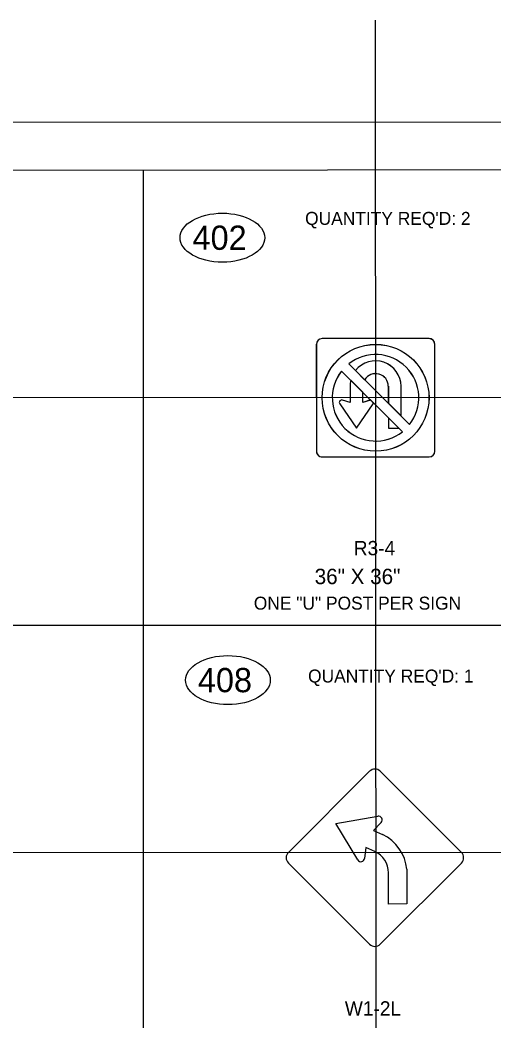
# Model space of a CAD drawing. Extents: x 1977705 to 1981198, y 827296 to 829291.
# Drawn here: x 1979660.1 to 1979879, y 828320.6 to 828783.1 of the extents above; entities that cross this region are included whole.
import ezdxf

# ---------------------------------------------------------------- set-up
doc = ezdxf.new("R2010")
doc.units = 0
for name, color, linetype in [('Level 3', 7, 'Continuous'), ('Level 34', 7, 'Continuous'), ('Level 43', 7, 'Continuous'), ('Level 45', 7, 'Continuous'), ('Level 7', 7, 'Continuous')]:
    doc.layers.add(name, color=color, linetype=linetype)

# ---------------------------------------------------------------- blocks, each defined once
blk = doc.blocks.new('Exist No U Turn')
at = {"layer": 'Level 45'}
for p, q in [((-62.7, 56.3), (-62.7, -56.6)), ((56.3, 62.3), (-56.6, 62.3)), ((62.3, -56.6), (62.3, 56.3)), ((-28.5, 35.7), (35.7, -28.5)), ((-28.5, 35.7), (-28.5, 35.7)), ((-36.1, 28.1), (28.1, -36.1)), ((-36.1, 28.1), (-36.1, 28.1)), ((-21.3, 28.5), (-11.7, 18.9)), ((-21.3, 28.5), (-11.7, 18.9)), ((-21.3, 28.5), (-11.7, 18.9)), ((-11.7, 18.9), (-11.7, 18.9)), ((-11.7, 18.9), (-11.7, 18.9)), ((-11.7, 18.9), (-11.7, 18.9)), ((-2.2, -5.7), (-5.4, -2.5)), ((-2.7, -6.7), (-2.7, -6.7)), ((-2.7, -6.7), (-2.7, -6.7)), ((-56.6, -62.7), (56.3, -62.7))]:
    blk.add_line(p, q, dxfattribs=at)
for points in [[(-27, 11.9), (-27, -5.1), (-35, -2.6)], [(-27, 11.9), (-27, -5.1), (-35, -2.6)], [(-27, 11.9), (-27, -5.1), (-35, -2.6)], [(-2.2, -5.7), (-5.4, -2.5), (-13.6, -5.1), (-13.6, 5.7), (-26.3, 18.3)], [(-5.7, -2.6), (-13.6, -5.1), (-13.6, 5.7), (-26.3, 18.3)], [(-2.2, -5.7), (-5.4, -2.5), (-13.6, -5.1), (-13.6, 5.7), (-26.3, 18.3)], [(13.3, 11.9), (13.3, -6), (26.7, -19.5), (26.7, 11.9)], [(13.3, 11.9), (13.3, -6), (26.7, -19.5), (26.7, 11.9)], [(13.3, 11.9), (13.3, -6), (26.7, -19.5), (26.7, 11.9)], [(-38, -6.7), (-20.3, -32.4), (-2.7, -6.7)], [(-38, -6.7), (-20.3, -32.4), (-2.7, -6.7)], [(-38, -6.7), (-20.3, -32.4), (-2.7, -6.7)]]:
    blk.add_lwpolyline(points, dxfattribs=at)
blk.add_lwpolyline([(13.3, -21.2), (13.3, -32.4), (24.5, -32.4)], close=True, dxfattribs=at)
blk.add_lwpolyline([(13.3, -21.2), (13.3, -32.4), (24.5, -32.4)], close=True, dxfattribs=at)
blk.add_lwpolyline([(13.3, -21.2), (13.3, -32.4), (24.5, -32.4)], close=True, dxfattribs=at)
blk.add_circle((-0.2, -0.2), 56.4, dxfattribs=at)
for centre, radius, start, end in [((-56.6, 56.3), 6.05, 90, 180), ((56.3, 56.3), 6.05, 0, 90), ((-0.2, -0.2), 45.7, 321.7553, 128.2447), ((-0.2, 11.9), 26.9, 359.9928, 141.788), ((-0.2, 11.9), 26.9, 359.9928, 141.788), ((-0.2, 11.9), 26.9, 359.9928, 141.788), ((-0.2, -0.2), 45.7, 141.7553, 308.2447), ((-0.2, 11.9), 13.4, 0, 148.6739), ((-0.2, 11.9), 13.4, 0, 148.6739), ((-0.2, 11.9), 13.4, 0, 148.6739), ((-0.2, 11.9), 26.9, 166.2094, 180), ((-0.2, 11.9), 26.9, 166.2094, 180), ((-0.2, 11.9), 26.9, 166.2094, 180), ((-35.8, -5.2), 2.69, 72.3746, 214.4704), ((-35.8, -5.2), 2.69, 72.3746, 214.4704), ((-35.8, -5.2), 2.69, 72.3746, 214.4704), ((-4.9, -5.1), 2.67, 101.5336, 107.1991), ((-4.9, -5.1), 2.67, 101.5336, 107.1991), ((-4.9, -5.1), 2.67, 101.5336, 108.0305), ((-4.9, -5.2), 2.69, 325.4527, 348.1626), ((-4.9, -5.2), 2.69, 325.4527, 348.1626), ((-4.9, -5.2), 2.69, 325.4527, 348.1626), ((-56.6, -56.6), 6.05, 180, 270), ((56.3, -56.6), 6.05, 270, 0)]:
    blk.add_arc(centre, radius, start, end, dxfattribs=at)

msp = doc.modelspace()

# ---------------------------------------------------------------- linework, layer by layer
at = {"layer": 'Level 3'}
msp.add_lwpolyline([(1981020.16, 828736.58), (1979336.66, 828735.68), (1979337.25, 827640.68), (1981020.75, 827641.58)], close=True, dxfattribs=at)
at = {"layer": 'Level 34'}
for p, q in [((1979824.92, 827663.96), (1979824.32, 828783.14)), ((1980814.89, 828609.21), (1979481.21, 828608.49)), ((1981001.97, 828399.12), (1979481.32, 828398.3))]:
    msp.add_line(p, q, dxfattribs=at)
at = {"layer": 'Level 43'}
for p, q in [((1979796.98, 828633.27), (1979797.01, 828583.89)), ((1979849.01, 828635.94), (1979799.63, 828635.92)), ((1979851.68, 828583.92), (1979851.66, 828633.3)), ((1979811.95, 828624.29), (1979840.04, 828596.23)), ((1979811.95, 828624.29), (1979811.95, 828624.29)), ((1979808.63, 828620.96), (1979836.71, 828592.9)), ((1979808.63, 828620.96), (1979808.63, 828620.96)), ((1979815.09, 828621.15), (1979819.3, 828616.94)), ((1979815.09, 828621.15), (1979819.3, 828616.94)), ((1979819.3, 828616.94), (1979819.3, 828616.94)), ((1979819.3, 828616.94), (1979819.3, 828616.94)), ((1979823.43, 828606.17), (1979822.03, 828607.57)), ((1979823.24, 828605.75), (1979823.24, 828605.75)), ((1979799.66, 828581.24), (1979849.04, 828581.27))]:
    msp.add_line(p, q, dxfattribs=at)
for points in [[(1979821.9, 828607.53), (1979818.45, 828606.44), (1979818.45, 828611.14), (1979812.91, 828616.68)], [(1979823.43, 828606.17), (1979822.03, 828607.57), (1979818.45, 828606.44), (1979818.45, 828611.14), (1979812.91, 828616.68)], [(1979812.57, 828613.88), (1979812.58, 828606.43), (1979809.11, 828607.53)], [(1979812.57, 828613.88), (1979812.58, 828606.43), (1979809.11, 828607.53)], [(1979830.21, 828613.89), (1979830.21, 828606.04), (1979836.09, 828600.17), (1979836.09, 828613.89)], [(1979830.21, 828613.89), (1979830.21, 828606.04), (1979836.09, 828600.17), (1979836.09, 828613.89)], [(1979807.79, 828605.74), (1979815.52, 828594.48), (1979823.24, 828605.75)], [(1979807.79, 828605.74), (1979815.52, 828594.48), (1979823.24, 828605.75)]]:
    msp.add_lwpolyline(points, dxfattribs=at)
msp.add_lwpolyline([(1979830.22, 828599.39), (1979830.22, 828594.49), (1979835.12, 828594.49)], close=True, dxfattribs=at)
msp.add_lwpolyline([(1979830.22, 828599.39), (1979830.22, 828594.49), (1979835.12, 828594.49)], close=True, dxfattribs=at)
msp.add_lwpolyline([(1979830.22, 828599.39), (1979830.22, 828594.49), (1979835.12, 828594.49)], close=True, dxfattribs=at)
msp.add_circle((1979824.33, 828608.59), 24.69, dxfattribs=at)
for centre, radius, start, end in [((1979799.63, 828633.27), 2.65, 90.0308, 180.0308), ((1979849.01, 828633.3), 2.65, 0.0308, 90.0308), ((1979824.33, 828608.59), 19.99, 321.7861, 128.2755), ((1979824.33, 828613.88), 11.76, 0.0236, 141.8188), ((1979824.33, 828613.88), 11.76, 0.0236, 141.8188), ((1979824.33, 828608.59), 19.99, 141.7861, 308.2755), ((1979824.33, 828613.88), 5.88, 0.0308, 148.7047), ((1979824.33, 828613.88), 5.88, 0.0308, 148.7047), ((1979824.33, 828613.88), 11.76, 166.2402, 180.0308), ((1979824.33, 828613.88), 11.76, 166.2402, 180.0308), ((1979808.75, 828606.41), 1.18, 72.4054, 214.5012), ((1979808.75, 828606.41), 1.18, 72.4054, 214.5012), ((1979822.27, 828606.42), 1.17, 101.5644, 108.0613), ((1979822.27, 828606.42), 1.18, 325.4835, 348.1935), ((1979822.27, 828606.42), 1.18, 325.4835, 348.1935), ((1979799.65, 828583.89), 2.65, 180.0308, 270.0308), ((1979849.04, 828583.91), 2.65, 270.0308, 0.0308)]:
    msp.add_arc(centre, radius, start, end, dxfattribs=at)
at = {"layer": 'Level 45'}
for p, q in [((1979796.98, 828633.27), (1979797.01, 828583.89)), ((1979849.01, 828635.94), (1979799.63, 828635.92)), ((1979851.68, 828583.92), (1979851.66, 828633.3)), ((1979811.95, 828624.29), (1979840.04, 828596.23)), ((1979811.95, 828624.29), (1979811.95, 828624.29)), ((1979808.63, 828620.96), (1979836.71, 828592.9)), ((1979808.63, 828620.96), (1979808.63, 828620.96)), ((1979815.09, 828621.15), (1979819.3, 828616.94)), ((1979815.09, 828621.15), (1979819.3, 828616.94)), ((1979819.3, 828616.94), (1979819.3, 828616.94)), ((1979819.3, 828616.94), (1979819.3, 828616.94)), ((1979823.43, 828606.17), (1979822.03, 828607.57)), ((1979823.24, 828605.75), (1979823.24, 828605.75)), ((1979799.66, 828581.24), (1979849.04, 828581.27))]:
    msp.add_line(p, q, dxfattribs=at)
for points in [[(1979821.9, 828607.53), (1979818.45, 828606.44), (1979818.45, 828611.14), (1979812.91, 828616.68)], [(1979823.43, 828606.17), (1979822.03, 828607.57), (1979818.45, 828606.44), (1979818.45, 828611.14), (1979812.91, 828616.68)], [(1979812.57, 828613.88), (1979812.58, 828606.43), (1979809.11, 828607.53)], [(1979812.57, 828613.88), (1979812.58, 828606.43), (1979809.11, 828607.53)], [(1979830.21, 828613.89), (1979830.21, 828606.04), (1979836.09, 828600.17), (1979836.09, 828613.89)], [(1979830.21, 828613.89), (1979830.21, 828606.04), (1979836.09, 828600.17), (1979836.09, 828613.89)], [(1979807.79, 828605.74), (1979815.52, 828594.48), (1979823.24, 828605.75)], [(1979807.79, 828605.74), (1979815.52, 828594.48), (1979823.24, 828605.75)]]:
    msp.add_lwpolyline(points, dxfattribs=at)
msp.add_lwpolyline([(1979830.22, 828599.39), (1979830.22, 828594.49), (1979835.12, 828594.49)], close=True, dxfattribs=at)
msp.add_lwpolyline([(1979830.22, 828599.39), (1979830.22, 828594.49), (1979835.12, 828594.49)], close=True, dxfattribs=at)
msp.add_lwpolyline([(1979830.22, 828599.39), (1979830.22, 828594.49), (1979835.12, 828594.49)], close=True, dxfattribs=at)
msp.add_circle((1979824.33, 828608.59), 24.69, dxfattribs=at)
for centre, radius, start, end in [((1979799.63, 828633.27), 2.65, 90.0308, 180.0308), ((1979849.01, 828633.3), 2.65, 0.0308, 90.0308), ((1979824.33, 828608.59), 19.99, 321.7861, 128.2755), ((1979824.33, 828613.88), 11.76, 0.0236, 141.8188), ((1979824.33, 828613.88), 11.76, 0.0236, 141.8188), ((1979824.33, 828608.59), 19.99, 141.7861, 308.2755), ((1979824.33, 828613.88), 5.88, 0.0308, 148.7047), ((1979824.33, 828613.88), 5.88, 0.0308, 148.7047), ((1979824.33, 828613.88), 11.76, 166.2402, 180.0308), ((1979824.33, 828613.88), 11.76, 166.2402, 180.0308), ((1979808.75, 828606.41), 1.18, 72.4054, 214.5012), ((1979808.75, 828606.41), 1.18, 72.4054, 214.5012), ((1979822.27, 828606.42), 1.17, 101.5644, 108.0613), ((1979822.27, 828606.42), 1.18, 325.4835, 348.1935), ((1979822.27, 828606.42), 1.18, 325.4835, 348.1935), ((1979799.65, 828583.89), 2.65, 180.0308, 270.0308), ((1979849.04, 828583.91), 2.65, 270.0308, 0.0308)]:
    msp.add_arc(centre, radius, start, end, dxfattribs=at)
at = {"layer": 'Level 7'}
for p, q in [((1979815.09, 828621.15), (1979819.3, 828616.94)), ((1979819.3, 828616.94), (1979819.3, 828616.94)), ((1979823.24, 828605.75), (1979823.24, 828605.75)), ((1979805.97, 828411.92), (1979825.37, 828415.22)), ((1979816.11, 828395.04), (1979805.97, 828411.92)), ((1979825.37, 828415.22), (1979825.38, 828415.22)), ((1979819.86, 828400.85), (1979819.25, 828395.71)), ((1979823.92, 828399), (1979819.86, 828400.85)), ((1979826.49, 828356.09), (1979863.97, 828393.56)), ((1979830.31, 828374.68), (1979830.3, 828389.06)), ((1979838.81, 828386.54), (1979838.81, 828383.23)), ((1979838.81, 828383.23), (1979838.81, 828374.69)), ((1979838.81, 828374.69), (1979830.31, 828374.68))]:
    msp.add_line(p, q, dxfattribs=at)
msp.add_lwpolyline([(1981001.8, 828714.37), (1979502.12, 828713.56), (1979502.69, 827663.79), (1981002.36, 827664.6)], close=True, dxfattribs=at)
for points in [[(1979716.94, 828713.68), (1979716.94, 827663.9)], [(1979823.43, 828606.17), (1979822.03, 828607.57), (1979818.45, 828606.44), (1979818.45, 828611.14), (1979812.91, 828616.68)], [(1979812.57, 828613.88), (1979812.58, 828606.43), (1979809.11, 828607.53)], [(1979830.21, 828613.89), (1979830.21, 828606.04), (1979836.09, 828600.17), (1979836.09, 828613.89)], [(1979807.79, 828605.74), (1979815.52, 828594.48), (1979823.24, 828605.75)], [(1979502.24, 828503.56), (1980814.64, 828503.56)], [(1979821.54, 828435.99), (1979784.06, 828398.51)], [(1979863.97, 828398.51), (1979826.49, 828435.99)], [(1979826.91, 828412.4), (1979823.4, 828408.58), (1979827.47, 828406.73)], [(1979784.06, 828393.56), (1979821.54, 828356.09)], [(1979838.73, 828390.73), (1979838.73, 828390.73), (1979838.81, 828386.54), (1979838.81, 828386.54)]]:
    msp.add_lwpolyline(points, dxfattribs=at)
for centre, radius, start, end in [((1979824.33, 828613.88), 11.76, 0.0236, 141.8188), ((1979824.33, 828613.88), 5.88, 0.0308, 148.7047), ((1979824.33, 828613.88), 11.76, 166.2402, 180.0308), ((1979808.75, 828606.41), 1.18, 72.4054, 214.5012), ((1979822.27, 828606.42), 1.17, 101.5644, 107.23), ((1979822.27, 828606.42), 1.17, 101.5644, 107.23), ((1979822.27, 828606.42), 1.18, 325.4835, 348.1935), ((1979824.02, 828433.52), 3.5, 89.9935, 135), ((1979824.02, 828433.52), 3.5, 44.987, 89.9935), ((1979825.66, 828413.55), 1.7, 317.5401, 99.6621), ((1979819.36, 828389.05), 19.45, 4.9576, 65.3379), ((1979786.54, 828396.04), 3.5, 135, 225), ((1979819.36, 828389.05), 10.94, 0.0309, 65.3379), ((1979861.49, 828396.04), 3.5, 315, 45), ((1979817.56, 828395.91), 1.7, 211.0137, 353.1422), ((1979824.02, 828358.56), 3.5, 225, 270), ((1979824.02, 828358.56), 3.5, 270, 315)]:
    msp.add_arc(centre, radius, start, end, dxfattribs=at)
for centre in [(1979753.57, 828682.55), (1979756.14, 828478.14)]:
    msp.add_ellipse(centre, major_axis=(-19.54, 0), ratio=0.580127, dxfattribs=at)

# ---------------------------------------------------------------- block references
at = {"layer": 'Level 43', "xscale": 0.4375000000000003, "yscale": 0.43750000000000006, "rotation": 0.030813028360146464}
msp.add_blockref('Exist No U Turn', (1979824.41, 828608.67), dxfattribs=at)
msp.add_blockref('Exist No U Turn', (1979824.41, 828608.67), dxfattribs=at)

# ---------------------------------------------------------------- texts
at = {"layer": 'Level 7'}
for s, height, p in [("QUANTITY REQ'D: 2", 6, (1979791.78, 828688.48)), ('R3-4', 6.6, (1979814.26, 828535.83)), ('36" X 36"', 7.125, (1979796.2, 828522.47)), ('ONE "U" POST PER SIGN', 6, (1979768.09, 828510.69)), ("QUANTITY REQ'D: 1", 6, (1979793.15, 828477.01)), ('W1-2L', 6.6, (1979810.12, 828323.14))]:
    msp.add_text(s, height=height, dxfattribs=at).set_placement(p)
for s, p in [('402', (1979739.79, 828676.95)), ('408', (1979742.26, 828472.54))]:
    msp.add_text(s, height=11.202, rotation=359.9962, dxfattribs=at).set_placement(p)

doc.saveas('drawing.dxf')
